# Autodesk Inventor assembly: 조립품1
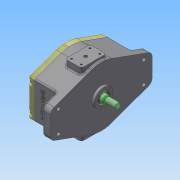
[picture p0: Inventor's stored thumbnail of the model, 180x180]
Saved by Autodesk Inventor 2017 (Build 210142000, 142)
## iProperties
Part Number: 조립품1
Material: 일반
Document SubType Name: Assembly
Designer: MRC
Author: MRC
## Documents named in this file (14)
- C:\Users\MRC\Desktop\731106V1012\조립품1.iam
- C:\Users\MRC\Desktop\731106V1012\부품1.ipt
- C:\Users\MRC\Downloads\731106V1012\축.ipt
- C:\Users\MRC\Downloads\731106V1012\평행 키 5x5x22.ipt
- C:\Users\MRC\Downloads\731106V1012\오일레스 부시.ipt
- C:\Users\MRC\Downloads\731106V1012\O링 G90.ipt
- C:\Users\MRC\Downloads\731106V1012\오일 실 14 25 4.ipt
- C:\Users\MRC\Downloads\731106V1012\DU 부시.ipt
- C:\Users\MRC\Downloads\731106V1012\내접기어.ipt
- C:\Users\MRC\Downloads\731106V1012\크레센트.ipt
- C:\Users\MRC\Downloads\731106V1012\스퍼기어.ipt
- C:\Users\MRC\Downloads\731106V1012\육각 소켓 머리 볼트 M4 x 30.ipt
- C:\Users\MRC\Downloads\731106V1012\커버.ipt
- C:\Users\MRC\Downloads\731106V1012\육각 소켓 머리 볼트 M6 x 12.ipt
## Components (2 placed, 2 different names)
1. O링 G90:1
2. DU 부시:2
